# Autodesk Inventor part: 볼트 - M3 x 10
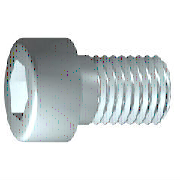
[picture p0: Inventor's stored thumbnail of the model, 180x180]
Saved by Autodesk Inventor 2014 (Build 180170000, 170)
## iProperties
Created: 2012-02
Part Number: 볼트 - M3 x 10
Material: 스테인리스강
Description: 6각 소켓 머리 캡 나사
Document SubType Name: Modeling
Standard: ISO 4762
Designer: mduedu
Standard Revision: Fourth edition 2004-03-01
Standards Organization: ISO
Language: ko-KR
Size Designation: M3 x 10
Categories: <MemberInstance><Categories><Category DisplayName="조임쇠" InternalName="e4da775c-781d-43d5-af7c-5136215cf5a6" Mnemonic="FSTN"><Category DisplayName="볼트" InternalN
Density: 8.08 g/cm^3
Mass: 1.0701 g
Surface Area: 2.01851 cm^2
Volume: 0.132438 cm^3
Appearance: 반광택
IsCustomPart: 0
Author: mduedu
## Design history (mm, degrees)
sketch "스케치1"
  geometry: L1 (-0.867, 0)-(10, 0); L2 (10, 0)-(10, 1.5); L3 (10, 1.5)-(1.25, 1.5); L4 (1.25, 1.5)-(0.943, 1.5); L5 (0.943, 1.5)-(0, 1.5); L6 (0, 1.5)-(0, 2.75); L7 (0, 2.75)-(-3, 2.75); L8 (-3, 2.75)-(-3, 1.443); L9 (-3, 1.443)-(-1.7, 1.443); L10 (-1.7, 1.443)-(-0.867, 0); L11 (-5.6, 0)-(12.6, 0) reference; L12 (0, -0.55)-(0, 3.3) reference; L13 (1.25, 1.5)-(0, 1.5)
  constraints: 22 end point, 6 parallel, 2 collinear, 2 perpendicular, 1 horizontal, 1 point on line
  dimensions: "d1" = 8.75 distance from line of L3.end L2 (= GEL); "d2" = 0.30683 distance of L4.end L3.end (computed from GAL); "d3" = 3 distance between parallel lines of L8 L6 (= KOH); "d4" = 1.3 distance of L8.end L9.end (= INTI); "d5" = 60 deg angle of L10 L1; "d6" = 3 diameter of L3 L1 (= GD); "d7" = 3 diameter of L5 L1 (= BDM); "d8" = 2.88675 diameter of L9 L1 (= 1.1547 x SW); "d9" = 5.5 diameter of L7 L1 (= KOD); "d26" = 10 distance between parallel lines of L12 L2 (= NLG)
revolve "본체" sketch "스케치1" stored, may be unused: angle "d10" = 90 deg
sketch "스케치2"
  geometry: L1 (0, -3.85)-(0, 3.85) reference; L2 (-3.85, 0)-(3.85, 0) reference; L3 (1.443, 0)-(0.722, -1.25); L4 (0.722, -1.25)-(-0.722, -1.25); L5 (-0.722, -1.25)-(-1.443, 0); L6 (-1.443, 0)-(-0.722, 1.25); L7 (-0.722, 1.25)-(0.722, 1.25); L8 (0.722, 1.25)-(1.443, 0); 2 further points
  constraints: 12 end point, 1 coincident, 1 horizontal alignment, 1 point on line, 12 other
extrude "슬롯" join sketch "스케치2" stored distance "d11" = 10; taper "d12" = 0 deg
workplane "Work Plane1"
fillet "Fillet2" dims "d30" = 0.1 (= R)
body "Solid1"
fillet "모깎기1" dims "d17" = 0.3 (= RR)
feature "스레드" dims "d13" = 8.75 (= GEL), "d14" = 0
chamfer "모따기1" distance "d15" = 0.30673 (= -0.5 x SPD + 0.5 x GD); stored, may be unused: second distance "d16" = 0.30673 (= GUL), angle "d27" = 45 deg
other parameters: "GD" = 3 [user parameter; used in 2 equation terms], "NLG" = 10 [user parameter; used in 1 equation term], "GEL" = 8.75 [user parameter; used in 2 equation terms], "KOD" = 5.5 [user parameter; used in 1 equation term], "KOH" = 3 [user parameter; used in 1 equation term], "INTI" = 1.3 [user parameter; used in 1 equation term], "GAL" = 0.30673 (= 0.61345 x PTC) [user parameter; used in 1 equation term], "GUL" = 0.30673 (= 0.61345 x PTC) [user parameter; used in 1 equation term], "BDM" = 3 (= NND) [user parameter; used in 1 equation term], "SW" = 2.5 [user parameter; used in 2 equation terms], "RR" = 0.3 [user parameter; used in 1 equation term], "SPD" = 2.38655 (= NND - 1.2269 x PTC) [user parameter; used in 1 equation term], "d19" = 0, "d28" = 0, "d29" = 0, "R" = 0.1 [user parameter; used in 1 equation term], "TOA" = 30 deg [user parameter], "GD1" = 2.38655 (= THREADDIA - 1.2269 x PTC) [user parameter], "THREADDIA" = 3 [user parameter; used in 1 equation term], "FAWI" = 45 deg [user parameter], "PTC" = 0.5 [user parameter; used in 5 equation terms], "NND" = 3 [user parameter; used in 2 equation terms], "E0" = 2.8875 (= 1.155 x SW) [user parameter]
